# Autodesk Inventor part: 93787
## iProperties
Author: Administrator
Shininess: 64.0
Angle Display Precision: 2
Document Length Units: 11272
Document Angle Units: 11286
Document Time Units: 11279
Document Mass Units: 11290
Document Length Units Precision: 3
Document Angle Units Precision: 2
Compacted: True
PropertySet Name: _Private Model Information
Created: 2002-03
Part Number: 93787
Material: Stainless Steel, 440C
Document SubType Name: Modeling
Designer: Administrator
Control State: 0
Master: False
Checked Out: False
PropertySet Name: Design Tracking Control
Density: 0.0
Volumn: 0.0
Area: 0.0
PropertySet Name: Model Information
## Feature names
1. Revolution1
